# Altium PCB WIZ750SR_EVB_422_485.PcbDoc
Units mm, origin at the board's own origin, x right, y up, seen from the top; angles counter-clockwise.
Board outline 73 x 65 mm, 2 copper layers (Top Layer, Bottom Layer), stack 0.325 mm thick; 59 components, 42 nets, 205 pads, 96 vias.
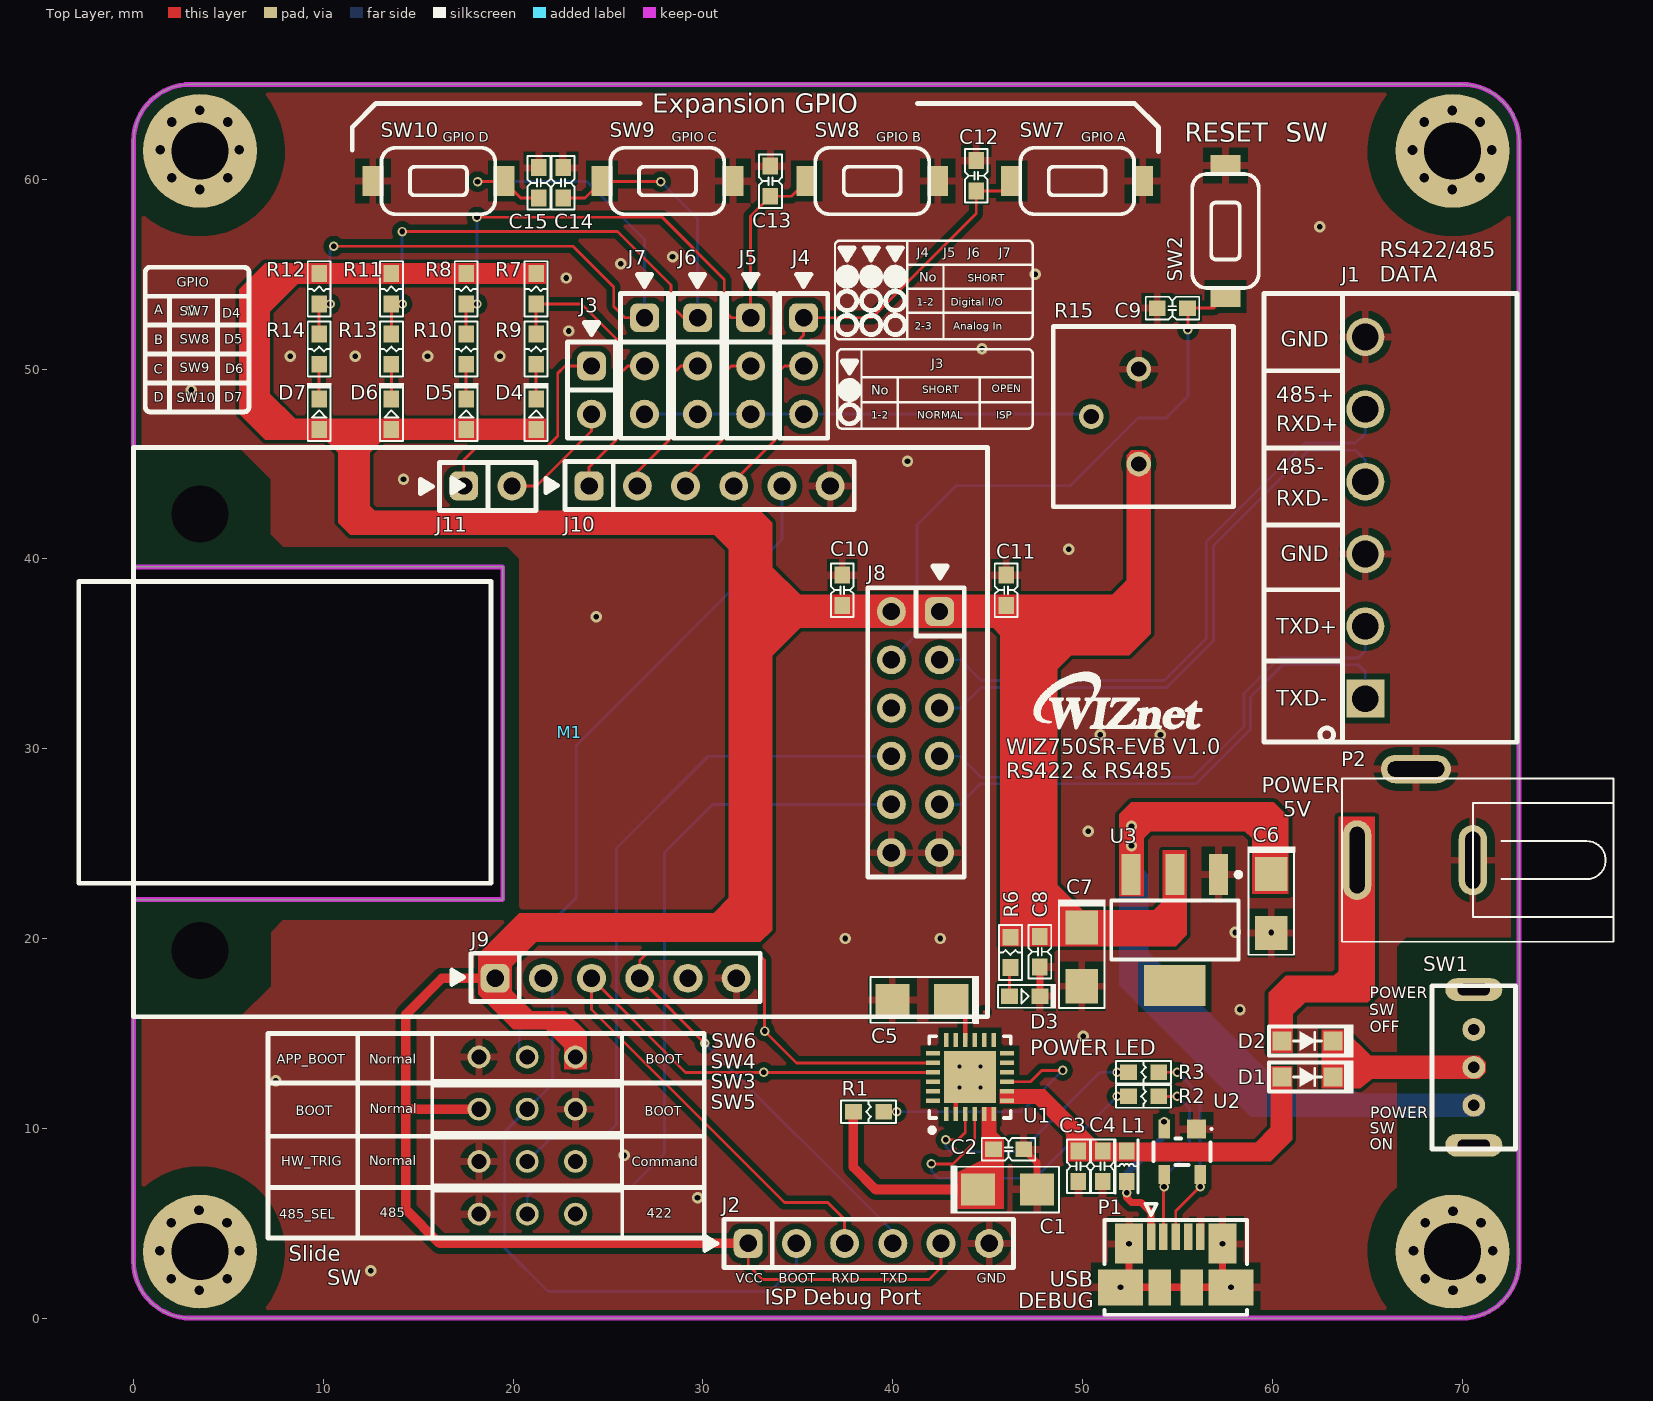
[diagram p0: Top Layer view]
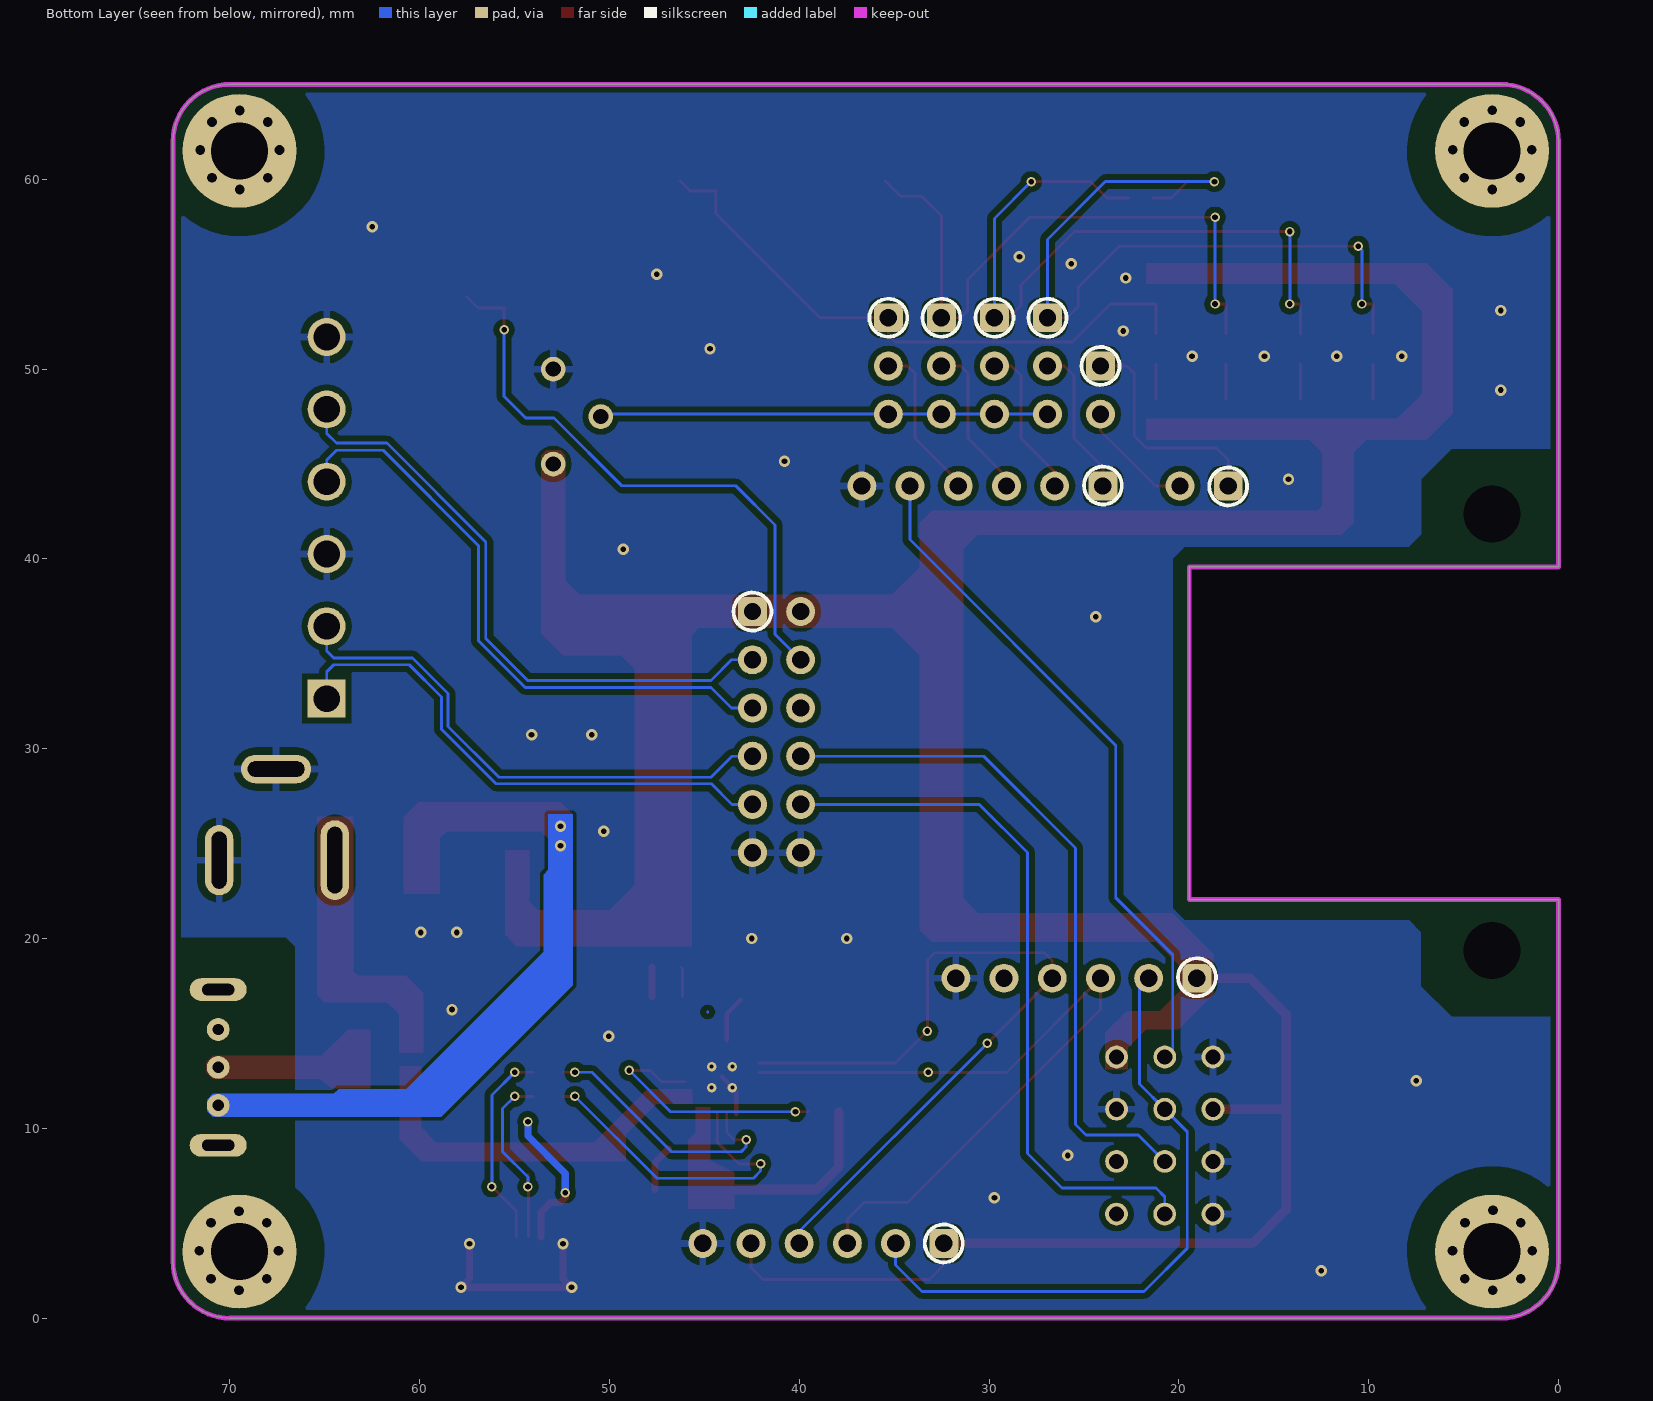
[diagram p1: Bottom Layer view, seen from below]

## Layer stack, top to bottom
Top Solder: solder mask 0.0102, Solder Resist, Dk 3.5
Top Layer: signal copper 0.0356
Dielectric 1: core 0.254, FR-4, Dk 4.2
Bottom Layer: signal copper 0.0356
Bottom Solder: solder mask 0.0102, Solder Resist, Dk 3.5

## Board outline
0,3 ccw(c3,3) 3,0 70,0 70,-0.003 ccw(c70,2.997) 73,2.997 73,62.001 ccw(c70,62.001) 70,65.001 70,65 3,65 ccw(c3,62) 0,62 0,39.575 19.45,39.575 19.45,22.05 0,22.05

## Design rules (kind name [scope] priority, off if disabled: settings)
Clearance [All] p1: gap=0.15 except(0.205: Track-Region SMDPad-Region THPad-Region Via-Region Fill-Region Poly-Region Region-Region; 0.3: Track-Poly SMDPad-Poly THPad-Poly Via-Poly Fill-Poly Poly-Poly; 0.381: Arc-Poly)
HoleSize [All] p1: absolutevalues=TRUE maxlimit=4.064 minlimit=0.025 maxpercent=80.000 minpercent=20.000
MinimumSolderMaskSliver [All] p1: minsoldermaskwidth=0.1
PlaneClearance [All] p1: clearance=0.381
PlaneConnect [All] p1: planeconnectstyle=Direct reliefexpansion=0.508 reliefentries=4 reliefconductorwidth=0.254 reliefairgap=0.254
PolygonConnect PolygonConnect_2 [IsPad vs IsNamedPolygon('TOPGND') or IsNamedPolygon('BOTGND')] p1: connectstyle=Relief reliefconductorwidth=0.381 reliefentries=4 polygonreliefangle="90 Angle" airgapwidth=0.381
PolygonConnect PolygonConnect_1 [IsVia] p2: connectstyle=Direct reliefconductorwidth=0.254 reliefentries=4 polygonreliefangle="90 Angle" airgapwidth=0.254
PolygonConnect [All] p3: connectstyle=Relief reliefconductorwidth=0.381 reliefentries=4 polygonreliefangle="90 Angle" airgapwidth=0.381
RoutingVias [All] p1: holewidth=0.3 width=0.5 viastyle="Through Hole" minholewidth=0.2 minwidth=0.5 maxholewidth=1 maxwidth=1.5
SilkToSilkClearance [All] p1: silktosilkclearance=0.1
SilkToSolderMaskClearance [IsPad] p1: minsilkscreentomaskgap=0 clearancetoexposedcopper=TRUE
SolderMaskExpansion [All] p1: expansion=0.1
Width [All] p1: maxlimit=0.508 minlimit=0.15 preferedwidth=0.508 minimp=50.000000 maximp=50.000000 favimp=50.000000
24 further rules are at their usual default settings.

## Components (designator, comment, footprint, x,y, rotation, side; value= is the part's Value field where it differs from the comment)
C1 "4.7uF/16V" "CAP-A Size" 46.05,6.775 r0 top
C2 "0.1uF" CAP-0603 46.1,8.9 r180 top
C3 "0.1uF" CAP-0603 49.784,8.001 r90 top
C4 "1uF" CAP-0603 51.054,8.001 r90 top
C5 "4.7uF/16V" "CAP-A Size" 41.529,16.764 r180 top
C6 "10uF/16V" "CAP-A Size" 59.944,21.844 r270 top
C7 "10uF/16V" "CAP-A Size" 49.959,19.037 r270 top
C8 "0.1uF" CAP-0603 47.752,19.304 r90 top
C9 "0.1uF" CAP-0603 54.737,53.213 r0 top
C10 "0.1uF" CAP-0603 37.338,38.354 r270 top
C11 "0.1uF" CAP-0603 45.974,38.354 r270 top
C12 "0.1uF" CAP-0603 44.398,60.186 r270 top
C13 "0.1uF" CAP-0603 33.558,59.903 r270 top
C14 "0.1uF" CAP-0603 22.631,59.814 r270 top
C15 "0.1uF" CAP-0603 21.356,59.814 r270 top
D1 "BAT60A" D-BAT60A/SOD-323 61.849,12.7 r0 top (schematic designator D3)
D2 "BAT60A" D-BAT60A/SOD-323 61.849,14.605 r0 top (schematic designator D4)
D3 "GREEN-0603" LED-0603-RED 46.957,16.952 r0 top (schematic designator D5)
D4 "GREEN-0603" LED-0603-GREEN 21.209,47.625 r90 top (schematic designator D6)
D5 "GREEN-0603" LED-0603-GREEN 17.526,47.625 r90 top (schematic designator D7)
D6 "GREEN-0603" LED-0603-GREEN 13.589,47.625 r90 top (schematic designator D8)
D7 "GREEN-0603" LED-0603-GREEN 9.779,47.625 r90 top (schematic designator D9)
J1 "ECH381R 6P" ECH381R_6P 64.897,44.069 r270 top
J2 "2.54mm 1x6 Pin Header DIP" IDC-1X6 32.385,3.937 r0 top
J3 "2.54mm 1x2 Pin Header DIP" IDC-1X2 24.13,50.165 r270 top
J4 "2.54mm 1x3 Pin Header DIP" IDC-1X3 35.306,52.705 r270 top
J5 "2.54mm 1x3 Pin Header DIP" IDC-1X3 32.512,52.705 r270 top
J6 "2.54mm 1x3 Pin Header DIP" IDC-1X3 29.718,52.705 r270 top
J7 "2.54mm 1x3 Pin Header DIP" IDC-1X3 26.924,52.705 r270 top
L1 "HH-1M1608-121JT" IND-0603 52.324,8.001 r90 top
M1 "WIZ750SR_422/485" WIZ750SR_V1.0_232/485 0,15.875 r0 top
P1 "47346-0001" USB-MICRO-B(SMD) 54.908,0.175 r90 top
P2 "DC-JACK 2pi" "DC-JACK 2pi" 67.564,24.13 r90 top
R1 "4.7K" RES-0603 38.725,10.875 r180 top
R2 "22R" RES-0603 53.213,11.684 r180 top
R3 "22R" RES-0603 53.213,12.954 r180 top
R6 "330R" RES-0603 46.203,19.266 r270 top
R7 "4.7K" RES-0603 21.209,54.229 r90 top
R8 "4.7K" RES-0603 17.526,54.229 r90 top
R9 "330R" RES-0603 21.209,51.054 r90 top
R10 "330R" RES-0603 17.526,51.054 r90 top
R11 "4.7K" RES-0603 13.589,54.229 r90 top
R12 "4.7K" RES-0603 9.779,54.229 r90 top
R13 "330R" RES-0603 13.589,51.054 r90 top
R14 "330R" RES-0603 9.779,51.054 r90 top
R15 "WIW3386P" WIW3386P 52.959,47.498 r270 top
SW1 "SK-12D02" SK-12D02 70.612,13.208 r90 top
SW2 "IT-1101NHA-180G" IT-1101NHA 57.531,57.277 r90 top
SW3 "ITS-12H" ITS-12H 20.743,8.256 r180 top
SW4 "ITS-12H" ITS-12H 20.743,11.006 r0 top
SW5 "ITS-12H" ITS-12H 20.745,5.482 r180 top
SW6 "ITS-12H" ITS-12H 20.743,13.756 r180 top
SW7 "IT-1101NHA-180G" IT-1101NHA 49.716,59.908 r180 top
SW8 "IT-1101NHA-180G" IT-1101NHA 38.921,59.908 r180 top
SW9 "IT-1101NHA-180G" IT-1101NHA 28.126,59.908 r180 top
SW10 "IT-1101NHA-180G" IT-1101NHA 16.061,59.908 r0 top
U1 "CP2104-GM" CP2104_QFN24_PAD 44.069,12.7 r90 top
U2 "SP0503BAHTG" SP0503BAHTG 55.245,8.763 r270 top
U3 "IL1117C-33ET" IL1117C-33ET 54.864,20.447 r270 top

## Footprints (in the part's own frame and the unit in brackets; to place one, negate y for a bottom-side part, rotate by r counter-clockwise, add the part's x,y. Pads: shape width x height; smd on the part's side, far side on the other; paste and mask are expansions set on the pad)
CAP-0603 [mm] "Ceramic CAP 0603(1608)"
  rect 0.89x0.82 smd: 1(-0.8,0) 2(0.8,0)
  silkscreen extent -1.41,-0.6 1.41,0.6, body extent -0.93,-0.41 0.93,0.41, height 0.81
"CAP-A Size" [mm] "Tantal CAP A Size EIA/IECQ 3216"
  rect 1.8x1.7 smd: 1(-1.55,0) 2(1.55,0)
  silkscreen extent -3,-1.25 2.7,1.25, body extent -1.67,-0.78 1.72,0.82, height 1.75
CP2104_QFN24_PAD [mm] "QFN, 24-Leads, Body 4.00x4.00mm, Pitch 0.50mm, Thermal Pad 2.75x2.75mm, IPC Medium Density"
  rect 0.75x0.25 smd: 1(-1.95,1.25) 2(-1.95,0.75) 3(-1.95,0.25) 4(-1.95,-0.25) 5(-1.95,-0.75) 6(-1.95,-1.25) 13(1.95,-1.25) 14(1.95,-0.75) 15(1.95,-0.25) 16(1.95,0.25) 17(1.95,0.75) 18(1.95,1.25)
  rect 0.25x0.75 smd: 7(-1.25,-1.95) 8(-0.75,-1.95) 9(-0.25,-1.95) 10(0.25,-1.95) 11(0.75,-1.95) 12(1.25,-1.95) 19(1.25,1.95) 20(0.75,1.95) 21(0.25,1.95) 22(-0.25,1.95) 23(-0.75,1.95) 24(-1.25,1.95)
  rect 2.75x2.75 smd: 25(0,0)
  silkscreen extent -2.92,-2.15 2.15,2.15, body extent -2,-2 2,2, height 0.8
D-BAT60A/SOD-323 [mm]
  rect 1x1 smd: 1(1.35,0) 2(-1.35,0)
  silkscreen extent -2.03,-0.86 2.41,0.86, body extent -1.35,-0.68 1.35,0.67, height 0.79
"DC-JACK 2pi" [mm] "DC-JACK 2pi"
  oval 4.2x1.5 hole 0.8 slot 3.5 at 0 deg: 1(0,3.1)
  oval 1.5x3.7 hole 0.8 slot 3 at 90 deg: 2(4.8,0)
  oval 3.7x1.5 hole 0.8 slot 3 at 0 deg: 3(0,-3)
  silkscreen extent -4.3,-10.4 4.3,3.9, body extent -4.42,-10.49 5.05,3.99, height 11.18
ECH381R_6P [mm] "Headers(Sockets) for pluggable terminal blocks"
  rect 2x2 hole 1.4: 1(11.43,0)
  round 2 hole 1.4: 2(7.62,0) 3(3.81,0) 4(0,0) 5(-3.81,0) 6(-7.62,0)
  silkscreen extent -9.92,-2.39 13.73,8, body extent -10.13,-1.3 13.92,7.9, height 7.9
IDC-1X2 [mil]
  rrect50% 60x60 hole 36: 1(0,0)
  round 60 hole 36: 2(100,0)
  silkscreen extent -90,-50 150,50, body extent -49,-49 151,51, height 336
IDC-1X3 [mil]
  rrect50% 60x60 hole 36: 1(0,0)
  round 60 hole 36: 2(100,0) 3(200,0)
  silkscreen extent -90,-50 250,50, body extent -46,-49 254,49, height 323
IDC-1X6 [mil] "6-Way 2.54 mm Male Header"
  rrect50% 60x60 hole 36: 1(0,0)
  round 60 hole 36: 2(100,0) 3(200,0) 4(300,0) 5(400,0) 6(500,0)
  silkscreen extent -90,-50 550,50, body extent -49,-49 551,51, height 336
IL1117C-33ET [mm] "SOT223, 4-Leads, Body 6.45x7.80mm (avg), Pitch 2.30mm, IPC Medium Density"
  rect 2.15x1 smd: 1(-2.925,2.3) 2(-2.925,0) 3(-2.925,-2.3)
  rect 2.15x3.25 smd: 4(2.925,0)
  silkscreen extent -3.05,-3.35 1.55,3.48, body extent -3.54,-3.25 3.54,3.25, height 1.65
IND-0603 [mm]
  rect 0.89x0.82 smd: 1(-0.8,0) 2(0.8,0)
  silkscreen extent -1.4,-0.6 1.4,0.6, body extent -0.8,-0.4 0.8,0.4, height 0.95
IT-1101NHA [mm]
  rect 1.1x1.6 smd: 1(-3.45,0) 2(3.45,0)
  silkscreen extent -3,-1.75 3,1.75, body extent -3.05,-1.85 3.05,1.85, height 2.5
ITS-12H [mm] "Silde Switch"
  round 1.2 hole 0.8: 1(0,0) 2(-2.54,0) 3(2.54,0)
  silkscreen extent -5,-1.25 5,1.25, body extent -5,-1.22 5,1.22, height 6.4
LED-0603-GREEN [mm] "LED-0603-GREEN"
  rect 0.89x0.82 smd: 1(-0.8,0) 2(0.8,0)
  silkscreen extent -1.41,-0.65 1.65,0.65, body extent -0.85,-0.45 0.85,0.45, height 0.9
LED-0603-RED [mm] "LED-0603-RED"
  rect 0.89x0.82 smd: 1(-0.8,0) 2(0.8,0)
  silkscreen extent -1.41,-0.65 1.65,0.65, body extent -0.85,-0.45 0.85,0.45, height 0.9
RES-0603 [mm] "RES-0603"
  rect 0.89x0.82 smd: 1(-0.8,0) 2(0.8,0)
  silkscreen extent -1.45,-0.6 1.45,0.6, body extent -0.82,-0.41 0.82,0.41, height 0.46
SK-12D02 [mm] "Angle Type, DIP Switch, ON-ON, DC 50V, 0.3A"
  round 1.2 hole 0.6: 1(-2,0) 2(0,0) 3(2,0)
  oval 1.2x3 hole 0.6 slot 1.7 at 90 deg: 4(-4.1,0) 5(4.1,0)
  silkscreen extent -4.3,-2.2 4.3,2.2, body extent -4.31,-6.22 4.31,2.15, height 5
SP0503BAHTG [mm] "SOT143, 4-Leads, Body 2.92x2.37mm, Pitch 1.90mm, IPC Medium Density"
  rect 1x1 smd: 1(-1.2,0.75)
  rect 1x0.6 smd: 2(-1.2,-0.95) 3(1.2,-0.95) 4(1.2,0.95)
  silkscreen extent -1.25,-1.5 0.7,1.6, body extent -0.7,-1.52 0.7,1.52, height 1.22
USB-MICRO-B(SMD) [mm] "MOLEX SD-47346-001"
  rect 1.38x0.45 smd: 1(4.11,1.3) 2(4.11,0.65) 3(4.11,0) 4(4.11,-0.65) 5(4.11,-1.3)
  rect 2.1x1.475 smd: 6(3.75,2.462) 7(3.75,-2.462)
  rect 1.9x2.375 smd: 8(1.45,2.913) 11(1.45,-2.913)
  rect 1.9x1.175 smd: 9(1.45,0.837) 10(1.45,-0.837)
  silkscreen extent 0,-3.75 5.85,3.75, body extent -0.43,-4.1 5,4.1, height 2.98
WIW3386P [mm] "Potentiometer 10KR, Hongxing, 8mm shaft"
  round 1.3 hole 0.8: 1(2.5,0) 2(0,-2.5) 3(-2.5,0)
  silkscreen extent -4.75,-4.5 4.75,5, body extent -3.3,-3.3 3.3,3.75, height 4.7
WIZ750SR_V1.0_232/485 [mil] "WIZ750SR_V1.0, Serial to Ethernet Module, W7500P"
  round 0 hole 118.11: CH_GND(137.8,137.8) CH_GND(137.8,1043.31)
  rrect50% 60x60 hole 36: D1(1671.89,840.55) E1(945,1101.1) I1(750,80) W1(685,1101.1)
  round 60 hole 36: D2(1571.89,840.55) D3(1671.89,740.55) D4(1571.89,740.55) D5(1671.89,640.55) D6(1571.89,640.55) D7(1671.89,540.55) D8(1571.89,540.55) D9(1671.89,440.55) D10(1571.89,440.55) D11(1671.89,340.55) D12(1571.89,340.55) E2(1045,1101.1) E3(1145,1101.1) E4(1245,1101.1) E5(1345,1101.1) E6(1445,1101.1) I2(850,80) I3(950,80) I4(1050,80) I5(1150,80) I6(1250,80) W2(785,1101.1)
  silkscreen extent -114,0 1772,1181, body extent 625,29 1715,1149, height 325

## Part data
C1 C5 C6 C7: library part "CAP-A Size", "Tantla CAP A Size EIA/IECQ 3216"
C2 C3 C4 C8 C9 C10 C11 C12 C13 C14 C15: library part CAP-0603, "Ceramic CAP 0603(1608)"
D1 D2: library part DIODE-BAT60A, "Silicon Schottky Diode"
D3 D4 D5 D6 D7: library part LED-0603, "LED-0603"
J1: "Headers(Sockets) for pluggable terminal blocks"
J2: library part "Header 6", "Header, 6-Pin"
J3: library part "Header 2", "Header, 2-Pin"
L1: library part IND-0603, "Inductor 0603(1608)"
M1: library part WIZ750SR_V1.0_422/485, "Serial to ethernet module, 45mmx30mm, 422/485"
P1: "MICRO USB B Type"
R1 R2 R3 R6 R7 R8 R9 R10 R11 R12 R13 R14: library part RES-0603, "RES-0603"
R15: "Potentiometer"
SW1: "3 Port SW , SPDT ON-ON , 50V, 0.3A"
SW2 SW7 SW8 SW9 SW10: "TACT Switch (SMD)"
SW3 SW4 SW5 SW6: "Slide Switch"
U1: "USB to UART Bridge, SiliconLabs"
U2: "Little Fuse, Silicon Protection Array Products"
U3: "1A, 3.3V"

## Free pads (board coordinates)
  round 6 hole 3: ""(3.5,3.5) ""(3.5,61.5) ""(69.5,3.5) ""(69.5,61.5)

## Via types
v1: diameter 0.6, hole 0.3, Top Layer to Bottom Layer, tented both sides, 36 vias
v2: diameter 0.762, hole 0.508, Top Layer to Bottom Layer, tented both sides, 32 vias
v3: diameter 0.5, hole 0.3, Top Layer to Bottom Layer, tented both sides, 22 vias
v4: diameter 0.5, hole 0.2, Top Layer to Bottom Layer, 4 vias
v5: diameter 0.5, hole 0.3, Top Layer to Bottom Layer, 2 vias

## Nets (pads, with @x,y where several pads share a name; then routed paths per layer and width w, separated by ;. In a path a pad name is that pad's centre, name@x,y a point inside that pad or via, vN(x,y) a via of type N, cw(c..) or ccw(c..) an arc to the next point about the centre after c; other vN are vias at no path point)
5V: C6.1 SW1.1 U3.3
  other v1: 52.578,24.892 52.578,25.908
485+_RXD+: J1.5 M1.D3 | length 32.5
  Bottom Layer w0.15: M1.D3 43.565,34.685 44.65,33.6 54.301,33.6 56.515,35.814 56.515,40.894 61.722,46.101 64.389,46.101 64.897,46.609 J1.5
485-_RXD-: J1.4 M1.D5 | length 32.3
  Bottom Layer w0.15: M1.D5 43.575,32.145 44.655,33.225 54.434,33.225 56.896,35.687 56.896,40.696 61.92,45.72 64.389,45.72 64.897,45.212 J1.4
485_SEL: M1.D10 SW5.1 | length 37.9
  Bottom Layer w0.15: SW5.1 20.745,6.394 21.209,6.858 26.162,6.858 27.975,8.671 27.975,24.525 30.515,27.065 M1.D10
ADC0: J4.3 J5.3 J6.3 J7.3 R15.2 | length 23.6
  Bottom Layer w0.15: J7.3 J6.3 J5.3 J4.3 50.332,47.625 R15.2
APP_BOOT: M1.E5 SW6.1 | length 36
  Bottom Layer w0.15: SW6.1 20.32,14.179 20.32,19.145 23.325,22.15 23.325,30.175 34.163,41.013 M1.E5
BOOT: J2.2 M1.I2 SW4.1 | length 33.5
  Bottom Layer w0.15: M1.I2 22.075,17.422 22.075,12.338 SW4.1 19.558,9.821 19.558,3.683 21.844,1.397 33.528,1.397 34.925,2.794 J2.2
D+: P1.3 R3.1 U2.4 | length 11.3
  Top Layer w0.15: R3.1 v3(54.991,12.954) ; P1.3 54.908,5.637 v3(56.195,6.924) U2.4
  Bottom Layer w0.15: v3(54.991,12.954) 56.195,11.75 v3(56.195,6.924)
D-: P1.2 R2.1 U2.3 | length 9.8
  Top Layer w0.15: R2.1 v3(54.991,11.684) ; P1.2 54.258,6.887 v3(54.295,6.924) U2.3
  Bottom Layer w0.15: v3(54.295,6.924) 54.295,7.432 55.626,8.763 55.626,11.049 v3(54.991,11.684)
EXPANSION_GPIO_A: J4.2 M1.E4 | length 8.4
  Top Layer w0.15: M1.E4 31.623,44.069 33.909,46.355 33.909,49.784 34.29,50.165 J4.2
EXPANSION_GPIO_B: J5.2 M1.E3 | length 8.3
  Top Layer w0.15: M1.E3 29.083,44.323 31.115,46.355 31.115,49.784 31.496,50.165 J5.2
EXPANSION_GPIO_C: J6.2 M1.E2 | length 8.2
  Top Layer w0.15: M1.E2 26.543,44.577 28.321,46.355 28.321,49.657 28.829,50.165 J6.2
EXPANSION_GPIO_D: J7.2 M1.E1 | length 8.1
  Top Layer w0.15: M1.E1 24.003,44.831 25.527,46.355 25.527,49.657 26.035,50.165 J7.2
GND: C1.2 C2.1 C3.1 C4.1 C5.2 C6.2 C7.2 C8.1 C9.1 C10.1 C11.1 C12.1 C13.1 C14.1 C15.1 D3.2 J1.3 J1.6 J2.6 M1.D11 M1.D12 M1.E6 M1.I6 P1.5 P1.6 P1.7 P1.8 P1.9 P1.10 P1.11 P2.2 P2.3 R15.3 SW2.2 SW3.3 SW4.3 SW5.3 SW6.3 SW7.1 SW8.1 SW9.1 SW10.1 U1.2 U1.25 U2.1 U3.1 | length 17
  Top Layer w0.25: U1.2 43.319,11.95 v4(43.519,12.15) U1.25
  Top Layer w0.381: C2.1 47.6,8.2 C1.2 ; C8.1 47.752,16.957 D3.2 ; v1(52.446,3.925) 52.446,2.075 v1(51.995,1.625) P1.9 P1.10 v1(57.821,1.625) 57.37,2.075 v1(57.37,3.925)
  other v1: 12.5,2.5 29.718,6.35 25.848,8.572 7.5,12.5 50.038,14.859 58.293,16.256 37.5,20 42.5,20 58.039,20.32 59.944,20.32 50.3,25.65 50.927,30.734 54.102,30.734 24.384,36.957 49.276,40.513 14.224,44.196 40.775,45.15 3.048,48.895 8.255,50.673 11.684,50.673 15.494,50.673 19.304,50.673 44.7,51.075 22.927,52.006 3.048,53.086 22.8,54.8 47.5,55 25.675,55.55 28.4,55.925 62.5,57.5
  other v4: 44.619,12.15 43.519,13.25 44.619,13.25
HW_TRIG: M1.D8 SW3.1 | length 36.6
  Bottom Layer w0.15: SW3.1 22.139,9.652 24.892,9.652 25.45,10.21 25.45,24.775 30.28,29.605 M1.D8
LED_SW0: C12.2 J4.1 R7.1 R9.2 SW7.2 | length 32.2
  Top Layer w0.15: R9.2 R7.1 23.596,53.429 25.6,51.425 34.95,51.425 35.306,51.781 J4.1 38.905,52.705 44.398,58.198 C12.2 45.744,59.386 SW7.2
LED_SW1: C13.2 J5.1 R8.1 R10.2 SW8.2 | length 33.4
  Top Layer w0.15: R10.2 R8.1 v3(18.096,53.429) ; v3(18.096,57.996) 27.854,57.996 31.125,54.725 31.125,53.075 31.495,52.705 J5.1 32.512,58.057 C13.2 34.666,59.103 SW8.2
  Bottom Layer w0.15: v3(18.096,53.429) v3(18.096,57.996)
LED_SW2: C14.2 J6.1 R11.1 R13.2 SW9.2 | length 37.5
  Top Layer w0.15: R13.2 R11.1 v3(14.154,53.429) ; v3(14.154,57.246) 25.504,57.246 28.325,54.425 28.325,53.35 28.97,52.705 J6.1 ; C14.2 23.782,59.014 SW9.2 24.709,59.875 v3(27.775,59.875)
  Bottom Layer w0.15: v3(14.154,53.429) v3(14.154,57.246) ; v3(27.775,59.875) 29.718,57.932 J6.1
LED_SW3: C15.2 J7.1 R12.1 R14.2 SW10.2 | length 41.6
  Top Layer w0.15: R14.2 R12.1 v3(10.354,53.429) ; v3(10.55,56.475) 23.154,56.475 25.3,54.329 25.3,53.3 25.895,52.705 J7.1 ; v3(18.125,59.875) 19.478,59.875 SW10.2 20.405,59.014 C15.2
  Bottom Layer w0.15: v3(10.354,53.429) 10.354,56.279 v3(10.55,56.475) ; v3(18.125,59.875) 23.875,59.875 26.924,56.826 J7.1
NetC5_1: C5.1 U1.16 | length 2.4
  Top Layer w0.25: C5.1 43.819,16.024 U1.16
NetD1_1: D1.1 D2.1 SW1.2
NetD2_2: D2.2 P2.1
NetD3_1: D3.1 R6.2 | length 1.5
  Top Layer w0.15: D3.1 46.157,18.42 R6.2
NetD4_2: D4.2 R9.1 | length 1.8
  Top Layer w0.15: D4.2 R9.1
NetD5_2: D5.2 R10.1 | length 1.8
  Top Layer w0.15: D5.2 R10.1
NetD6_2: D6.2 R13.1 | length 1.8
  Top Layer w0.15: D6.2 R13.1
NetD7_2: D7.2 R14.1 | length 1.8
  Top Layer w0.15: D7.2 R14.1
NetL1_1: L1.1 P1.1 U2.2 | length 8.7
  Top Layer w0.381: L1.1 v3(52.324,6.604) 52.324,6.35 52.578,6.096 53.086,6.096 53.608,5.574 P1.1 ; U2.2 v3(54.295,10.353)
  Bottom Layer w0.381: v3(52.324,6.604) 52.324,7.62 54.295,9.591 v3(54.295,10.353)
NetR1_1: R1.1 U1.9 | length 13.5
  Top Layer w0.15: R1.1 v5(40.2,10.875) ; U1.9 47.25,12.45 47.85,13.05 v5(48.95,13.05)
  Bottom Layer w0.15: v5(40.2,10.875) 46.775,10.875 v5(48.95,13.05)
NRESET: C9.2 M1.D4 SW2.1 | length 31.6
  Top Layer w0.15: v3(55.55,52.075) 55.55,53.2 C9.2 56.917,53.213 SW2.1
  Bottom Layer w0.15: M1.D4 41.275,36.034 41.275,41.783 43.342,43.85 49.35,43.85 52.925,47.425 54.41,47.425 55.55,48.565 v3(55.55,52.075)
PHY_LINK: M1.D6
TXD+: J1.2 M1.D7 | length 28
  Bottom Layer w0.15: M1.D7 43.547,29.605 44.652,28.5 55.825,28.5 58.5,31.175 58.5,32.9 60.375,34.775 64.525,34.775 64.897,35.147 J1.2
TXD-: J1.1 M1.D9 | length 28
  Bottom Layer w0.15: M1.D9 43.547,27.065 44.632,28.15 55.975,28.15 58.85,31.025 58.85,32.725 60.55,34.425 64.525,34.425 64.897,34.053 J1.1
U_RXD: J2.3 M1.I3 U1.21 | length 40.9
  Top Layer w0.15: J2.3 37.465,5.207 36.576,6.096 34.29,6.096 24.13,16.256 M1.I3 29.087,12.95 v3(33.2,12.95) U1.21
U_TXD: J2.4 M1.I4 U1.20 | length 40.6
  Top Layer w0.15: v3(30.099,14.478) M1.I4 26.67,18.845 27.075,19.25 32.875,19.25 33.25,18.875 v3(33.25,15.125) 34.925,13.45 U1.20
  Bottom Layer w0.15: v3(30.099,14.478) 40.005,4.572 J2.4
USB_3.3V: C1.1 C2.2 R1.2 U1.5 U1.6 | length 10
  Top Layer w0.508: R1.2 37.925,7.95 39.1,6.775 C1.1
USB_5V: C3.2 C4.2 D1.2 L1.2 U1.7 U1.8
USB_D+: R3.2 U1.3 | length 14
  Top Layer w0.15: v3(42.799,9.398) 43.434,9.398 43.819,9.783 U1.3 ; v3(51.816,12.954) R3.2
  Bottom Layer w0.15: v3(42.799,9.398) 42.799,9.017 43.053,8.763 46.736,8.763 50.927,12.954 v3(51.816,12.954)
USB_D-: R2.2 U1.4 | length 16.9
  Top Layer w0.15: v3(42.037,8.128) 43.18,8.128 44.319,9.267 U1.4 ; v3(51.816,11.684) R2.2
  Bottom Layer w0.15: v3(42.037,8.128) 42.037,7.747 42.418,7.366 47.498,7.366 v3(51.816,11.684)
VDD_3.3V: C7.1 C8.2 C10.2 C11.2 D4.1 D5.1 D6.1 D7.1 J2.1 J2.5 M1.D1 M1.D2 M1.I1 R6.1 R7.2 R8.2 R11.2 R12.2 R15.1 SW4.2 SW6.2 U3.2 | length 51.5
  Top Layer w0.15: J2.1 32.385,2.794 33.147,2.032 41.91,2.032 42.545,2.667 J2.5
  Top Layer w0.508: 14.394,11.006 SW4.2 ; M1.I1 16.256,17.907 14.351,16.002 14.351,5.715 16.129,3.937 J2.1
W7500P_NRST: J3.2 M1.W2 | length 6.3
  Top Layer w0.15: M1.W2 21.237,43.843 24.13,46.736 J3.2
WDT_NRST: J3.1 M1.W1 | length 12.1
  Top Layer w0.15: M1.W1 17.399,45.212 18.034,45.847 21.717,45.847 22.352,46.482 22.352,49.784 22.733,50.165 J3.1
pads on no net: M1.CH_GND M1.I5 P1.4 SW1.3 SW1.4 SW1.5 SW3.2 SW5.2 U1.1 U1.10 U1.11 U1.12 U1.13 U1.14 U1.15 U1.17 U1.18 U1.19 U1.22 U1.23 U1.24 U3.4
copper on no net: | length 0
  Top Layer w0.15: 44.819,16.119 44.825,16.125
  Bottom Layer w0.15: 44.821,16.129 44.825,16.125
  other v2: 3.468,1.463 69.52,1.473 1.995,2.074 4.941,2.074 68.047,2.083 70.993,2.083 1.385,3.546 5.588,3.556 67.437,3.556 71.603,3.556 1.995,5.019 68.047,5.029 70.993,5.029 4.928,5.029 69.52,5.639 3.45,5.675 69.469,59.461 3.493,59.463 2.02,60.073 4.966,60.073 67.996,60.071 70.942,60.071 67.386,61.544 71.552,61.544 1.41,61.546 5.576,61.546 67.996,63.017 70.942,63.017 2.02,63.019 4.966,63.019 3.493,63.629 69.469,63.627

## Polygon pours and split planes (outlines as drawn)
GND on Top Layer "TOPGND" (solid, remove dead copper, pour order 2): -2.413,66.802 -2.286,66.929 76.2,66.929 76.2,-1.524 75.946,-1.778 -2.921,-1.778
GND on Bottom Layer "BOTGND" (solid, remove dead copper, pour order 4): -2.413,66.929 76.2,66.929 76.073,66.802 76.073,-1.524 -2.794,-1.524 -2.921,-1.651

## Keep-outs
Keep-Out Layer:
  lines w0.254: 70,-0.003 ccw(c70,2.997) 73,2.997 73,62.001 ccw(c70,62.001) 70,65.001 ; 70,0 3,0 cw(c3,3) 0,3 0,22.05 19.45,22.05 19.45,39.575 0,39.575 0,62 cw(c3,62) 3,65 70,65

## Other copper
Top Layer:
  region net USB_5V: 45.65,12.065 45.65,11.303 47.498,11.303 49.149,9.652 49.149,8.275 59.925,8.275 61.05,9.4 61.05,13.275 59.925,13.275 59.925,10.05 59.125,9.25 50.821,9.25 48.006,12.065
  pour cut-out: 5.611,45.811 -0.012,45.811 -0.012,39.636 7.239,39.636 19.525,39.636 19.45,22.05 7.25,22.05 7.25,21.5 7.25,20.955 7.239,20.32 7.874,20.955 19.685,20.955 20.32,21.59 20.32,40.005 19.685,40.64 7.885,40.64 7.239,41.286 7.239,44.183
  pour cut-out: 66.548,-0.127 71.423,-0.127 73,1.45 73,7.023 73,20.066 67.056,20.066 66.548,19.558
  region net VDD_3.3V: 51.562,38.1 52.324,38.862 52.324,45.466 52.578,45.72 53.34,45.72 53.594,45.466 53.594,36.068 52.451,34.925 49.403,34.925 48.675,34.197 48.675,22.825 50,21.5 53.758,21.5 54.229,21.971 54.229,24.638 55.499,24.638 55.499,21.59 55.499,20.193 54.906,19.6 45.675,19.6 45.675,35.986 45.286,36.375 35.125,36.375 33.655,34.905 33.655,20.447 33.033,19.825 21.225,19.825 19.939,18.539 19.939,17.236 21,16.175 22.75,16.175 23.875,15.05 23.875,13.125 22.7,13.125 22.7,14.25 21.725,15.225 20,15.225 18.161,17.064 18.161,17.526 18.161,19.177 20.32,21.336 30.561,21.336 31.369,22.144 31.369,40.513 30.607,41.275 11.43,41.275 10.795,41.91 10.795,45.593 10.105,46.283 6.93,46.283 5.575,47.638 5.575,54.216 6.934,55.575 21.717,55.575 21.717,54.5 8.653,54.5 7.175,53.022 7.175,48.705 8.509,47.371 21.717,47.371 21.717,46.283 13.136,46.283 12.446,45.593 12.446,42.799 12.7,42.545 31.369,42.545 33.02,42.545 33.655,41.91 33.655,39.57 35.125,38.1
  region net 5V: 52.578,27.178 60.071,27.178 60.833,26.416 60.833,25.908 60.833,22.352 58.928,22.352 58.928,25.273 58.547,25.654 53.594,25.654 53.213,25.273 53.213,22.225 51.943,22.225 51.943,26.543
  region net NetD1_1: 62.6,15.2 63.8,15.2 65.175,13.825 70.9,13.825 71.25,13.475 71.25,12.95 70.9,12.6 65.25,12.6 64.625,12.1 62.625,12.1 62.6,12.125
  region net USB_3.3V: 43.425,7.675 44.7,8.313 44.7,9.575 44.7,11.1 45.45,11.1 45.45,9.8 45.85,9.4 45.85,5.775 43.425,5.775
  region net NetD2_2: 65.405,26.416 63.5,26.416 63.5,21.971 63.5,18.288 63.246,18.034 60.706,18.034 59.817,17.145 59.817,16.51 59.817,15.24 59.817,13.97 61.087,13.97 61.087,15.24 61.087,16.002 61.722,16.637 65.024,16.637 65.405,17.018 65.405,21.971
  pour cut-out: 7.251,22.05 0,22.05 0,15.875 5.635,15.875 7.251,17.491
  pour cut-out: 7.998,3.617 ccw(c3.5,3.5) 3.5,8 ccw(c3.5,3.5) -0.997,3.328 ccw(c3.818,3.328) 3.314,-1.46 ccw(c2.905,3.617)
  pour cut-out: 65.002,3.617 cw(c69.5,3.5) 69.5,8 cw(c69.5,3.5) 73.997,3.328 cw(c69.182,3.328) 69.686,-1.46 cw(c70.095,3.617)
  pour cut-out: 65.002,61.383 ccw(c69.5,61.5) 69.5,57 ccw(c69.5,61.5) 73.997,61.672 ccw(c69.182,61.672) 69.686,66.46 ccw(c70.095,61.383)
  pour cut-out: 7.998,61.383 cw(c3.5,61.5) 3.5,57 cw(c3.5,61.5) -0.997,61.672 cw(c3.818,61.672) 3.314,66.46 cw(c2.905,61.383)
Bottom Layer:
  pour cut-out: 5.611,45.811 -0.012,45.811 -0.012,39.636 7.239,39.636 19.525,39.636 19.45,22.05 7.25,22.05 7.25,21.5 7.25,20.955 7.239,20.32 7.874,20.955 19.685,20.955 20.32,21.59 20.32,40.005 19.685,40.64 7.885,40.64 7.239,41.286 7.239,44.183
  pour cut-out: 66.548,-0.127 71.423,-0.127 73,1.45 73,7.023 73,20.066 67.056,20.066 66.548,19.558
  region net 5V: 71.2,11.5 71.2,10.9 70.9,10.6 58.869,10.6 51.943,17.526 51.943,26.543 53.213,26.543 53.213,23.622 53.467,23.368 53.467,19.304 60.706,12.065 64.262,12.065 64.516,11.811 70.889,11.811
  pour cut-out: 7.251,22.05 0,22.05 0,15.875 5.635,15.875 7.251,17.491
  pour cut-out: 7.998,3.617 ccw(c3.5,3.5) 3.5,8 ccw(c3.5,3.5) -0.997,3.328 ccw(c3.818,3.328) 3.314,-1.46 ccw(c2.905,3.617)
  pour cut-out: 65.002,3.617 cw(c69.5,3.5) 69.5,8 cw(c69.5,3.5) 73.997,3.328 cw(c69.182,3.328) 69.686,-1.46 cw(c70.095,3.617)
  pour cut-out: 65.002,61.383 ccw(c69.5,61.5) 69.5,57 ccw(c69.5,61.5) 73.997,61.672 ccw(c69.182,61.672) 69.686,66.46 ccw(c70.095,61.383)
  pour cut-out: 7.998,61.383 cw(c3.5,61.5) 3.5,57 cw(c3.5,61.5) -0.997,61.672 cw(c3.818,61.672) 3.314,66.46 cw(c2.905,61.383)

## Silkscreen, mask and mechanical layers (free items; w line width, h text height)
Top Overlay:
  drawing of 1377 lines, arcs and shapes, not listed
  text "Expansion GPIO" at 27.33,63.492 h1
  text "RESET" at 55.372,61.976 h1
  text "SW" at 60.706,61.976 h1
  text "GPIO D" at 16.281,61.968 h0.5
  text "GPIO C" at 28.346,61.968 h0.5
  text "GPIO B" at 39.141,61.968 h0.5
  text "GPIO A" at 49.936,61.968 h0.5
  text "J4" at 41.275,55.88 h0.5
  text "J5" at 42.672,55.88 h0.5
  text "J6" at 43.942,55.88 h0.5
  text "J7" at 45.593,55.88 h0.5
  text "RS422/485" at 65.659,55.88 h0.8
  text "No" at 41.402,54.61 h0.5
  text "SHORT" at 43.942,54.61 h0.4
  text "DATA" at 65.659,54.61 h0.8
  text "GPIO" at 2.274,54.35 h0.5
  text "1-2" at 41.275,53.34 h0.4
  text "Digital I/O" at 43.053,53.34 h0.4
  text "A" at 1.088,52.888 h0.5
  text "SW7" at 2.438,52.813 h0.5
  text "D4" at 4.688,52.713 h0.5
  text "2-3" at 41.148,52.07 h0.4
  text "Analog In" at 43.18,52.07 h0.4
  text "SW8" at 2.438,51.338 h0.5
  text "D5" at 4.788,51.338 h0.5
  text "B" at 1.088,51.313 h0.5
  text "GND" at 60.452,51.181 h0.8
  text "J3" at 42.037,50.038 h0.5
  text "SW9" at 2.438,49.838 h0.5
  text "D6" at 4.826,49.784 h0.5
  text "C" at 1.063,49.763 h0.5
  text "OPEN" at 45.212,48.768 h0.4
  text "SHORT" at 41.55,48.725 h0.4
  text "No" at 38.862,48.641 h0.5
  text "D" at 1.063,48.288 h0.5
  text "D7" at 4.788,48.288 h0.5
  text "SW10" at 2.286,48.26 h0.5
  text "485+" at 60.198,48.26 h0.8
  text "1-2" at 38.862,47.371 h0.4
  text "NORMAL" at 41.3,47.375 h0.4
  text "ISP" at 45.466,47.371 h0.4
  text "RXD+" at 60.198,46.736 h0.8
  text "485-" at 60.198,44.45 h0.8
  text "RXD-" at 60.198,42.799 h0.8
  text "J11" at 15.926,41.427 h0.76
  text "J10" at 22.657,41.427 h0.76
  text "GND" at 60.452,39.878 h0.8
  text "J8" at 38.659,38.887 h0.76
  text "TXD+" at 60.198,36.068 h0.8
  text "TXD-" at 60.198,32.258 h0.8
  text "WIZ750SR-EVB V1.0" at 45.974,29.718 h0.8
  text "RS422 & RS485" at 45.974,28.448 h0.8
  text "POWER" at 59.436,27.686 h0.8
  text "5V" at 60.579,26.416 h0.8
  text "J9" at 17.78,19.558 h0.76
  text "POWER" at 65.126,16.84 h0.6
  text "SW" at 65.1,15.951 h0.6
  text "OFF" at 65.126,15.062 h0.6
  text "POWER LED" at 47.244,13.843 h0.8
  text "APP_BOOT" at 7.539,13.415 h0.5
  text "Normal" at 12.416,13.415 h0.5
  text "BOOT" at 26.996,13.415 h0.5
  text "Normal" at 12.446,10.795 h0.5
  text "BOOT" at 8.555,10.697 h0.5
  text "BOOT" at 26.924,10.668 h0.5
  text "POWER" at 65.151,10.541 h0.6
  text "SW" at 65.121,9.726 h0.6
  text "ON" at 65.121,8.876 h0.6
  text "Normal" at 12.416,8.056 h0.5
  text "HW_TRIG" at 7.793,8.03 h0.5
  text "Command" at 26.259,8.005 h0.5
  text "485" at 12.975,5.325 h0.5
  text "422" at 27.05,5.3 h0.5
  text "485_SEL" at 7.666,5.226 h0.5
  text "Slide" at 8.168,2.994 h0.8
  text "VCC" at 31.725,1.875 h0.5
  text "BOOT" at 34.006,1.875 h0.5
  text "RXD" at 36.775,1.875 h0.5
  text "TXD" at 39.375,1.875 h0.5
  text "GND" at 44.425,1.875 h0.5
  text "SW" at 10.2,1.724 h0.8
  text "USB" at 48.26,1.651 h0.8
  text "ISP Debug Port" at 33.25,0.7 h0.8
  text "DEBUG" at 46.609,0.508 h0.8
Mechanical 2:
  text "BOARD NAME : WIZ750SR_EVB 422/485" at 0.762,83.185 h1.52
  text "VERSION : V1.0" at 0.762,80.391 h1.52
  text "SIZE : 73mmX65mmX1.6T" at 0.762,77.597 h1.52
  text "LAYER : 2L  1.6T" at 0.762,74.93 h1.52
  text "GERBER DATE : 2016.06.27" at 0.762,72.136 h1.52
  text "Designed by WIZnet" at 0.508,68.072 h5.08

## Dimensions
0,3 to 73,2.997 on Keep-Out Layer
3,0 to 3,65 on Keep-Out Layer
